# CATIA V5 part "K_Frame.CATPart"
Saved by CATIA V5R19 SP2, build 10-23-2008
Part number: Frame
Bounding box of the stored display mesh (mm): x -80 to 80, y -60 to 60, z 0 to 15
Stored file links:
  G:\Khaled_CFAO_2011\ST2M\ST2M_GR1\bgaltie\bgaltie\Khaled\CAD_thinkMOTION\K_Frame.CATPart
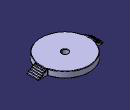
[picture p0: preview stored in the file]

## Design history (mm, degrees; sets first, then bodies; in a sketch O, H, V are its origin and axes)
AxisSystem1: origin (0, 0, 0), X (1, 0, 0), Y (0, 1, 0), Z (0, 0, 1)
Body1 (main body)
  Sketch1 on XY plane of AxisSystem1, origin (0, 0, 0), H (1, 0, 0), V (0, 1, 0)
    arc A1 centre (0, 0) radius 60 from (0, -60) to (58.0948, -15) ccw
    line L1 (7.5, 0) -> (45, 0)
    point P1 (45, 0)
    point P2 (45, 0)
    line L2 (45, 0) -> (80, 0)
    line L3 (80, 0) -> (80, -15)
    line L4 (80, -15) -> (58.0948, -15)
    reference intersected line E1 through (0, 0) direction (0, 1) from YZ plane of AxisSystem1
    line L5 (0, -7.5) -> (0, -60)
    arc A2 centre (0, 0) radius 7.5 from (0, -7.5) to (7.5, 0) ccw
    point P7 (0, 0)
    reference projected line E2 through (0, 0) direction (0, 1) from edge [YZ plane of AxisSystem1 | XY plane of AxisSystem1]
    radius A1 = 60
    length L3 = 15
    distance L3 E1 = 80
    radius A2 = 7.5
    horizontal: L1 H, L2 H, L4 H
    coincidence: P2 L1, P1 P2, P7 O, H L1, E2 L5
    vertical: L3 V, L5 V
  Pad1: profile Sketch1, direction (0, 0, 1), length 15
  Sketch2 on face of Pad1 from Sketch1.L4, origin (0, -15, 0), H (1, 0, 0), V (0, 0, 1)
    line L1 (80, 2.5) -> (76, 2.5)
    line L2 (76, 2.5) -> (76, 5)
    line L3 (76, 5) -> (72, 5)
    line L4 (72, 5) -> (72, 7.5)
    line L5 (72, 7.5) -> (68, 7.5)
    line L6 (68, 7.5) -> (68, 10)
    line L7 (68, 10) -> (64, 10)
    line L8 (64, 10) -> (64, 12.5)
    line L9 (64, 12.5) -> (60, 12.5)
    line L10 (60, 12.5) -> (60, 15)
    line L11 (80, 2.5) -> (80, 15)
    line L12 (80, 15) -> (60, 15)
    reference projected line E1 (58.0948, 15) -> (80, 15) from edge [face of Pad1 from Sketch1.L4 | end face of Pad1]
    reference projected line E2 (80, 0) -> (80, 15) from edge [face of Pad1 from Sketch1.L3 | face of Pad1 from Sketch1.L4]
    length L2 = 2.5
    length L1 = 4
    length L4 = 2.5
    length L6 = 2.5
    length L8 = 2.5
    length L10 = 2.5
    length L3 = 4
    length L5 = 4
    length L7 = 4
    length L9 = 4
    distance L12 E1 = 0
    distance E2 L11 = 0
    horizontal: L1 H, L5 H, L7 H, L3 H, L9 H, L12 H
    vertical: L2 V, L4 V, L6 V, L10 V, L11 V, L8 V
  Pocket1: profile Sketch2, direction (0, 1, 0), through (limit type 6)
  Mirror1: of Pad1, Sketch1, Pocket1, Sketch2, about ZX plane of AxisSystem1
  Mirror2: of Pad1, Sketch1, Pocket1, Sketch2, about YZ plane of AxisSystem1
  CircPattern1: of Pad1, Sketch1, Pocket1, Sketch2, instances 2, angular step 180, axis from edge [ZX plane of AxisSystem1 | YZ plane of AxisSystem1]
  Fillet1: radius 1, on face of CircPattern1
  Fillet2: radius 1, on face of Pad1 from Sketch1.L4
